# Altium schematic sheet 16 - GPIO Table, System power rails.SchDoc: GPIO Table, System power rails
size A3; PageSetup: Record=PageOptions¦CenterHorizontal=True¦CenterVertical=True¦PrintScale=1.01¦XCorrection=1.00¦YCorrection=1.00¦PrintKind=0¦BorderSize=5000000¦LeftOffset=0¦BottomOffset=0¦Orientation=2¦PaperLength=4200¦PaperWidth=2970¦Scale=100¦PaperSource=15¦PrintQuality=600¦MediaType=1¦DitherType=10¦PrintScaleMode=1¦PaperKind=A3¦PaperIndex=8; Author: Juan Anzola; SheetNumber: 16; SheetTotal: 17
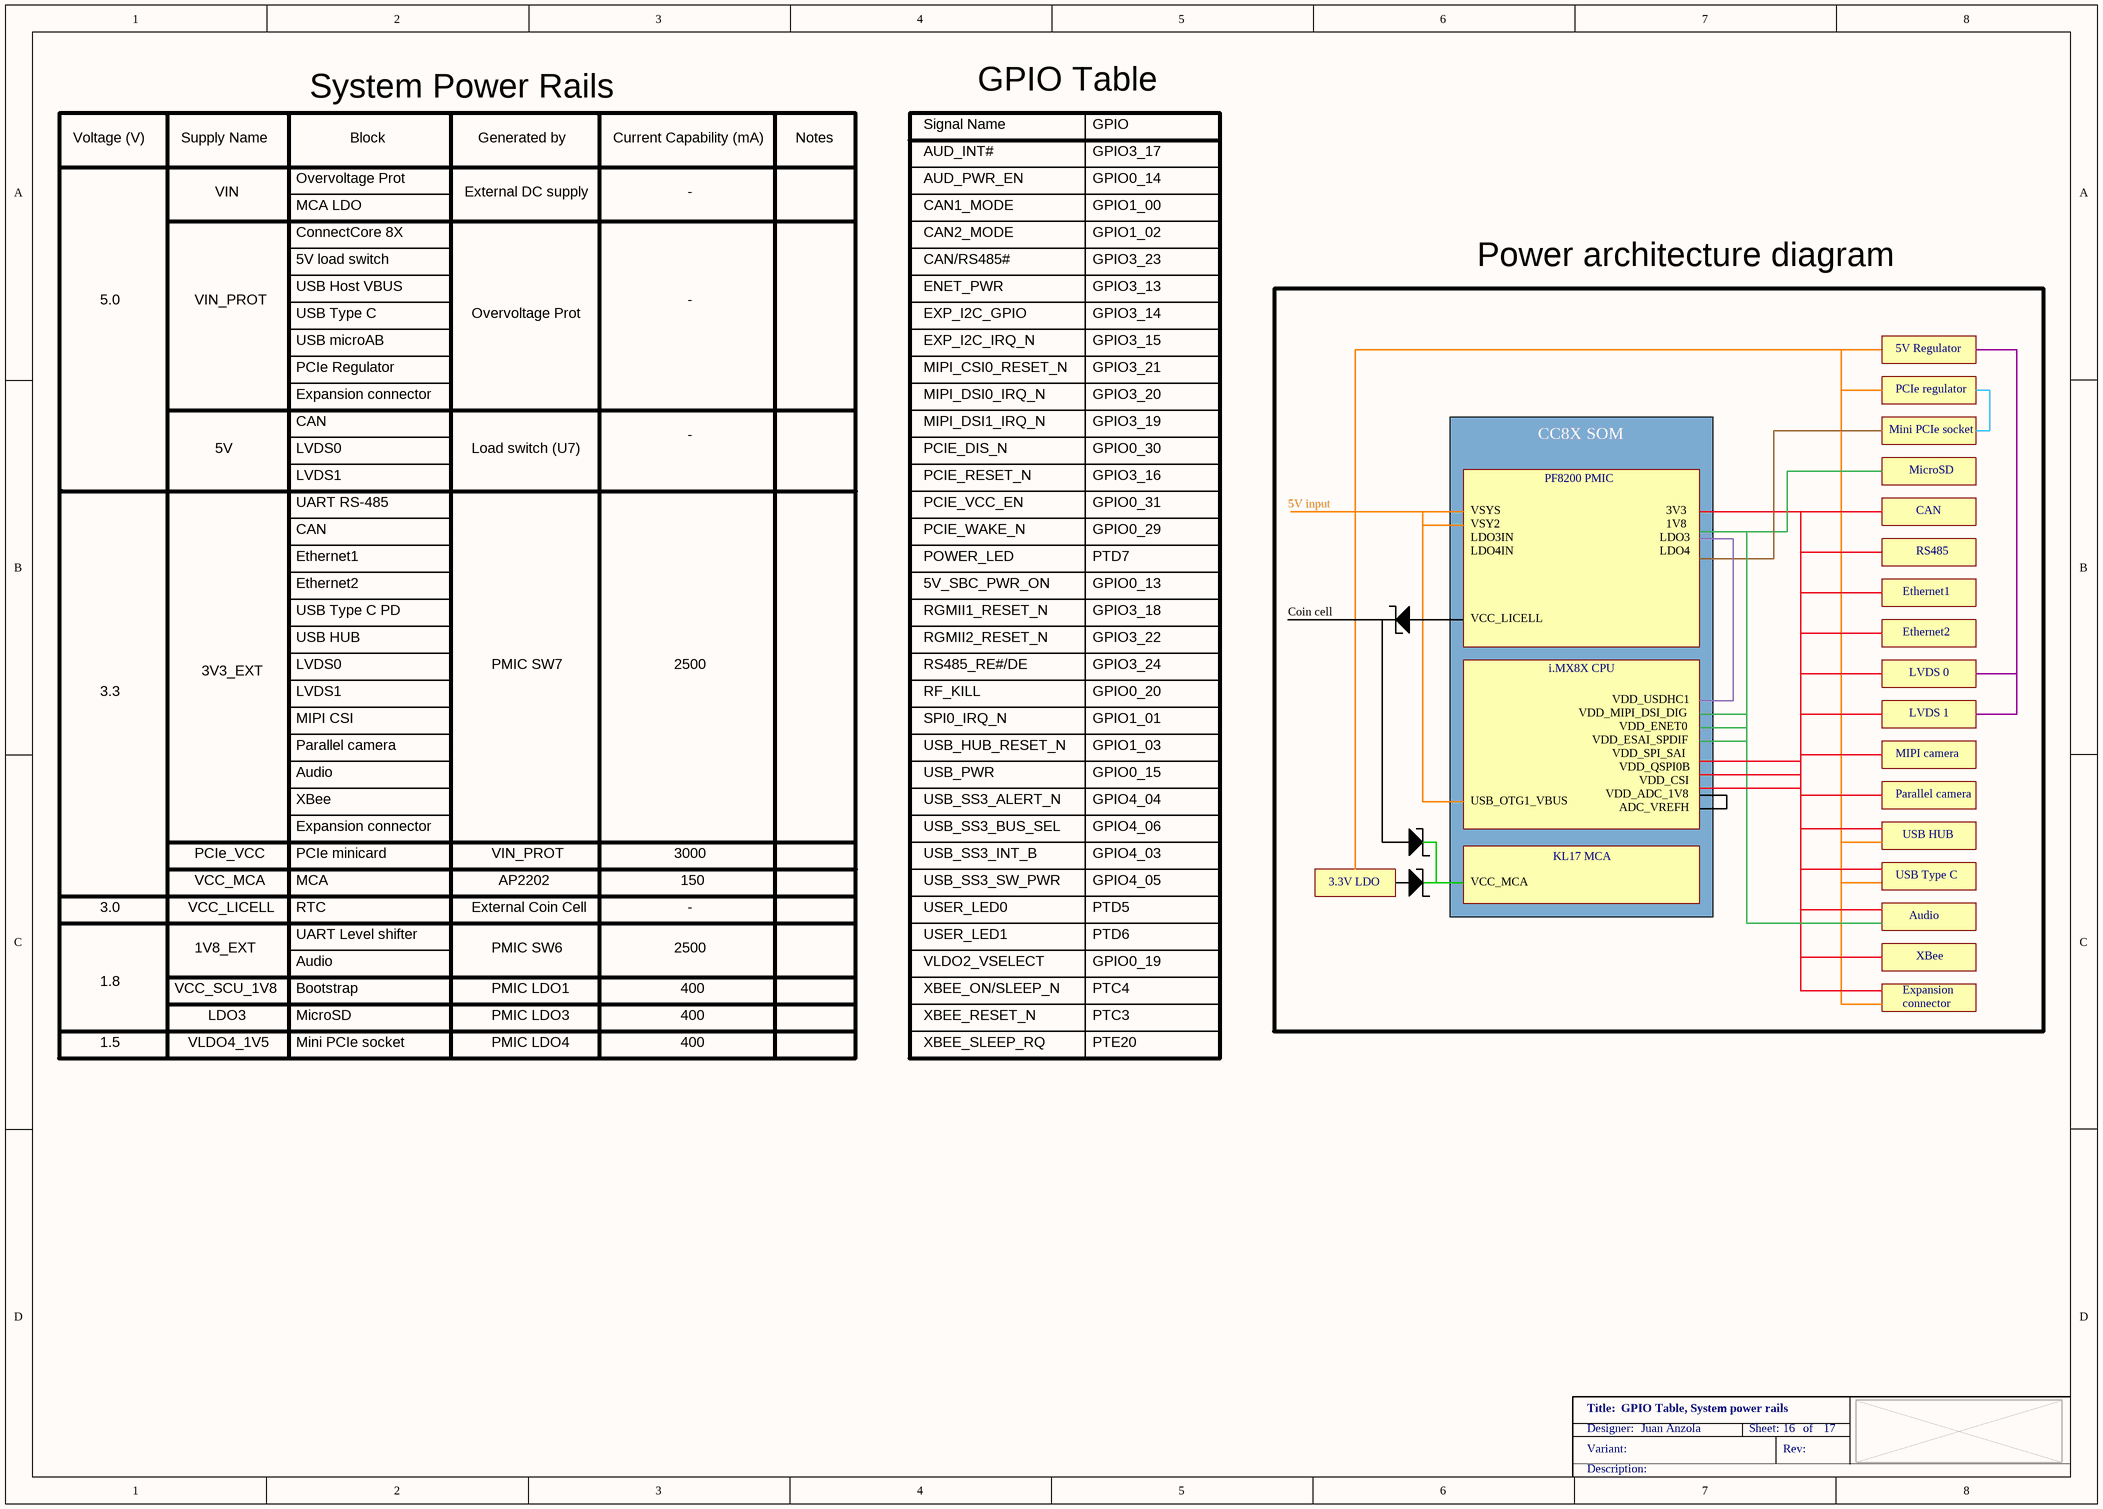
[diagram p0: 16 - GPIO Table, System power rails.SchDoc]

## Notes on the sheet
- System Power Rails
- GPIO Table
- Voltage (V)
- Supply Name
- Overvoltage Prot
- Block
- Generated by
- Current Capability (mA)
- Notes
- Signal Name
- AUD_PWR_EN
- AUD_INT#
- GPIO
- GPIO0_14
- GPIO3_17
- VIN
- MCA LDO
- ConnectCore 8X
- External DC supply
- -
- CAN2_MODE
- CAN1_MODE
- GPIO1_00
- GPIO1_02
- 5.0
- VIN_PROT
- USB Host VBUS
- USB Type C
- 5V load switch
- CAN/RS485#
- ENET_PWR
- EXP_I2C_GPIO
- GPIO3_13
- GPIO3_14
- GPIO3_23
- Power architecture diagram
- PCIe Regulator
- USB microAB
- MIPI_CSI0_RESET_N
- EXP_I2C_IRQ_N
- GPIO3_21
- GPIO3_15
- 5V Regulator
- 5V
- LVDS0
- Expansion connector
- CAN
- Load switch (U7)
- MIPI_DSI0_IRQ_N
- PCIE_DIS_N
- MIPI_DSI1_IRQ_N
- GPIO3_20
- GPIO0_30
- GPIO3_19
- CC8X SOM
- Mini PCIe socket
- PCIe regulator
- UART RS-485
- LVDS1
- PCIE_RESET_N
- PCIE_VCC_EN
- GPIO0_31
- GPIO3_16
- 5V input
- VSYS
- PF8200 PMIC
- 3V3
- MicroSD
- Ethernet1
- Ethernet2
- 5V_SBC_PWR_ON
- POWER_LED
- PCIE_WAKE_N
- GPIO0_13
- GPIO0_29
- PTD7
- VSY2
- LDO3IN
- LDO4IN
- LDO3
- LDO4
- 1V8
- RS485
- USB HUB
- USB Type C PD
- RGMII1_RESET_N
- RGMII2_RESET_N
- GPIO3_18
- GPIO3_22
- Coin cell
- VCC_LICELL
- 3.3
- 3V3_EXT
- MIPI CSI
- PMIC SW7
- 2500
- RS485_RE#/DE
- RF_KILL
- SPI0_IRQ_N
- GPIO0_20
- GPIO3_24
- GPIO1_01
- i.MX8X CPU
- VDD_MIPI_DSI_DIG
- VDD_USDHC1
- LVDS 0
- LVDS 1
- Parallel camera
- Audio
- USB_PWR
- USB_HUB_RESET_N
- GPIO0_15
- GPIO1_03
- VDD_ESAI_SPDIF
- VDD_SPI_SAI
- VDD_ENET0
- VDD_QSPI0B
- VDD_CSI
- MIPI camera
- PCIe_VCC
- XBee
- PCIe minicard
- 3000
- USB_SS3_INT_B
- USB_SS3_ALERT_N
- USB_SS3_BUS_SEL
- GPIO4_03
- GPIO4_04
- GPIO4_06
- USB_OTG1_VBUS
- VDD_ADC_1V8
- ADC_VREFH
- 3.0
- VCC_MCA
- MCA
- RTC
- External Coin Cell
- AP2202
- 150
- USER_LED0
- USB_SS3_SW_PWR
- GPIO4_05
- PTD5
- 3.3V LDO
- KL17 MCA
- 1.8
- VCC_SCU_1V8
- 1V8_EXT
- UART Level shifter
- Bootstrap
- PMIC LDO1
- PMIC SW6
- 400
- USER_LED1
- VLDO2_VSELECT
- XBEE_ON/SLEEP_N
- GPIO0_19
- PTC4
- PTD6
- Expansion
- 1.5
- VLDO4_1V5
- PMIC LDO4
- PMIC LDO3
- XBEE_SLEEP_RQ
- XBEE_RESET_N
- PTC3
- PTE20
- connector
